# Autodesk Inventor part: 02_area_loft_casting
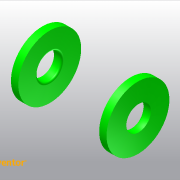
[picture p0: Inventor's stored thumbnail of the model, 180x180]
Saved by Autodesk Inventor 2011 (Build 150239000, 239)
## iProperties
Company: Autodesk
Created: 2007-01
Part Number: 02_area_loft_casting
Document SubType Name: Modeling
Designer: Lieven Grauls
Stock Number: 02_area_loft_finished
Project: Valve Techcamp 2008
Density: 1 g/cm^3
Mass: 1966.25 g
Surface Area: 2688.56 cm^2
Volume: 1966.25 cm^3
Author: Lieven Grauls
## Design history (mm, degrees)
node "02_are_loft_def_finished" dims "d0" = 10
feature "Sculpt1"
fillet "Fillet1" dims "d1" = 8
fillet "Fillet2" dims "d2" = 8, "d11" = 5
node "Volumenkörper1"
node "Volumenkörpern"
node "Oberflächenkörpern"
sketch "Sketch15"
  geometry: L1 (-80, 100)-(-46.5, 100) reference; L2 (-37.013, 96.7)-(-37.013, 60) reference; L3 (-37.013, 60)-(-35.513, 60) reference; L4 (-80, 113)-(-80, 100) reference; L5 (-46.5, 100)-(-46.5, 96.7) reference; L6 (-46.5, 96.7)-(-37.013, 96.7) reference; L7 (0, -22.6)-(0, 135.6) reference; L8 (-183.58, 0)-(30.597, 0) reference; L9 (-35.513, 60)-(-35.513, 0) reference; L10 (-35.513, 0)-(0, 0) reference
workplane "Work Plane6"
feature "RevolutionSrf2"
node "Flächen2"
feature "RevolutionSrf3"
node "Flächen3"
feature "OffsetSrf2" [RevolutionSrf]
node "Flächen4"
feature "RevolutionSrf1"
node "Flächen5"
feature "Flächen2::02_are_loft_def_finished" [RevolutionSrf]
node "Flächen6"
sketch "Sketch20"
  geometry: L1 (0, -22.6)-(0, 135.6) reference; L2 (-183.58, 0)-(30.597, 0) reference; L3 (-130, 0)-(-152.983, 0) reference; L4 (-128, 77.5)-(-114, 77.5) reference; L5 (-114, 77.5)-(-114, 45) reference; L6 (-114, 45)-(-107, 45) reference; L7 (-107, 45)-(-107, 100.638) reference; L8 (-128, 77.5)-(-128, 48) reference; L9 (-128, 48)-(-130, 48) reference; L10 (-130, 48)-(-130, 0) reference
other parameters: "d50" = 0.5, "d51" = 2, "d52" = 0
